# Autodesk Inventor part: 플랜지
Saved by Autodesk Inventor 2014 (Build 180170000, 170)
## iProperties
Created: 2026-09
Part Number: 플랜지
Material: 일반
Document SubType Name: Modeling
Designer: dg
Density: 1 g/cm^3
Appearance: 기본값
Author: dg
Author: jhkim
Creation Date: 2026-08-27
Sending System: Autodesk Inventor 2027
Preprocessor: ST-DEVELOPER v20.1
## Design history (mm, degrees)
node "플랜지1"
node "솔리드1"
node "기준1"
